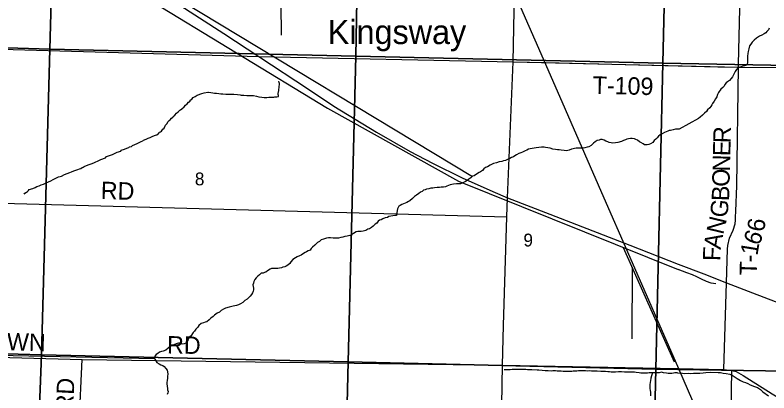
# Model space of a CAD drawing. Extents: x 1588073 to 2013523, y 1090242 to 1357120.
# Drawn here: x 1785512 to 1798510, y 1238801 to 1245314 of the extents above; entities that cross this region are included whole.
import ezdxf

# ---------------------------------------------------------------- set-up
doc = ezdxf.new("R2010")
doc.units = 0
for name, color, linetype in [('GM_X_County_Road', 7, 'Continuous'), ('GM_X_County_Road_Text', 7, 'Continuous'), ('GM_X_Interstate_Route', 7, 'Continuous'), ('GM_X_Minor_River', 7, 'Continuous'), ('GM_X_Rail_Line', 7, 'Continuous'), ('GM_X_Section', 7, 'Continuous'), ('GM_X_Section_Text', 7, 'Continuous'), ('GM_X_State_Route', 7, 'Continuous'), ('GM_X_Township', 7, 'Continuous'), ('GM_X_Township_Road', 7, 'Continuous'), ('GM_X_Township_Road_Text', 7, 'Continuous'), ('GM_X_Unincorporated_Text', 7, 'Continuous')]:
    doc.layers.add(name, color=color, linetype=linetype)

msp = doc.modelspace()

# ---------------------------------------------------------------- linework, layer by layer
at = {"layer": 'GM_X_County_Road'}
for points in [[(1783455, 1244777), (1789714, 1244599), (1794099, 1244508)], [(1783338, 1239471), (1786669, 1239379), (1793916, 1239280)], [(1793916, 1239280), (1796937, 1239222), (1797730, 1239206), (1797868, 1239189), (1797942, 1239170), (1798066, 1239102), (1798567, 1238786), (1799878, 1238002), (1800384, 1237717), (1800530, 1237645), (1800653, 1237609), (1800784, 1237606), (1801009, 1237631), (1801102, 1237626), (1801198, 1237597)], [(1797948, 1233819), (1797943, 1233923), (1797894, 1235681), (1797869, 1236898), (1797812, 1237011), (1797793, 1237062), (1797856, 1238490), (1797868, 1239189)]]:
    msp.add_lwpolyline(points, dxfattribs=at)
at = {"layer": 'GM_X_Interstate_Route'}
for points in [[(1785484, 1246915), (1785971, 1246718), (1786551, 1246463), (1787073, 1246207), (1787447, 1246011), (1788270, 1245539), (1789114, 1244996), (1789714, 1244599), (1790570, 1244034), (1791010, 1243743), (1791741, 1243297), (1792324, 1242961), (1792708, 1242760), (1793219, 1242506), (1793750, 1242273), (1794002, 1242166)], [(1794002, 1242166), (1794732, 1241883), (1796109, 1241345), (1796944, 1241022), (1797388, 1240851), (1797777, 1240701), (1798226, 1240528), (1798620, 1240376), (1799159, 1240168), (1799436, 1240060), (1799894, 1239880), (1800019, 1239834)]]:
    msp.add_lwpolyline(points, dxfattribs=at)
at = {"layer": 'GM_X_Minor_River'}
for p, q in [((1787308, 1245896), (1790896, 1243710)), ((1788371, 1245565), (1793400, 1242534)), ((1790097, 1245501), (1790098, 1244970)), ((1790896, 1243710), (1790896, 1243710)), ((1790896, 1243710), (1793156, 1242451)), ((1793156, 1242451), (1793156, 1242451)), ((1793156, 1242451), (1796942, 1240929)), ((1795997, 1241309), (1796878, 1239336)), ((1796149, 1240969), (1796147, 1239733)), ((1787915, 1239390), (1784794, 1239452))]:
    msp.add_line(p, q, dxfattribs=at)
for points in [[(1798512, 1245087), (1798502, 1245061), (1798471, 1245029), (1798455, 1245006), (1798428, 1244990), (1798390, 1244967), (1798345, 1244949), (1798296, 1244914), (1798257, 1244881), (1798223, 1244845), (1798196, 1244813), (1798177, 1244784), (1798164, 1244734), (1798154, 1244688), (1798147, 1244650), (1798142, 1244603), (1798139, 1244569), (1798138, 1244487), (1798121, 1244453), (1798087, 1244438), (1798059, 1244432), (1798030, 1244421), (1798006, 1244413), (1797982, 1244408), (1797951, 1244374), (1797930, 1244340), (1797912, 1244308), (1797897, 1244284), (1797883, 1244251), (1797860, 1244219), (1797827, 1244185), (1797797, 1244164), (1797770, 1244146), (1797748, 1244118), (1797737, 1244087), (1797713, 1244067), (1797682, 1244035), (1797641, 1243978), (1797624, 1243946), (1797611, 1243906), (1797587, 1243872), (1797564, 1243830), (1797539, 1243791), (1797524, 1243765), (1797506, 1243739), (1797493, 1243715), (1797453, 1243678), (1797434, 1243650), (1797401, 1243623), (1797365, 1243587), (1797324, 1243554), (1797293, 1243532), (1796964, 1243348)], [(1789023, 1243962), (1789059, 1243958), (1789073, 1243958), (1789095, 1243956), (1789145, 1243952), (1789207, 1243953), (1789281, 1243951), (1789349, 1243947), (1789391, 1243939), (1789411, 1243935), (1789433, 1243931), (1789455, 1243931), (1789509, 1243925), (1789563, 1243928), (1789625, 1243926), (1789673, 1243918), (1789717, 1243906), (1789767, 1243900), (1789805, 1243894), (1789820, 1243892), (1789852, 1243894), (1789886, 1243896), (1789934, 1243897), (1789958, 1243899), (1789972, 1243899), (1789992, 1243903), (1790010, 1243903), (1790028, 1243907), (1790052, 1243909), (1790054, 1243929), (1790049, 1243945), (1790047, 1243971), (1790055, 1243985), (1790059, 1244013), (1790061, 1244039), (1790063, 1244057), (1790067, 1244080), (1790071, 1244116), (1790071, 1244132), (1790067, 1244150), (1790057, 1244172)], [(1785668, 1242225), (1785682, 1242245), (1785710, 1242263), (1785728, 1242271), (1785744, 1242289), (1785756, 1242305), (1785818, 1242327), (1785856, 1242343), (1785888, 1242356), (1785926, 1242370), (1785964, 1242388), (1786000, 1242400), (1786039, 1242416), (1786089, 1242440), (1786127, 1242459), (1786167, 1242477), (1786205, 1242495), (1786259, 1242523), (1786287, 1242533), (1786315, 1242539), (1786365, 1242564), (1786459, 1242598), (1786485, 1242612), (1786525, 1242628), (1786593, 1242649), (1786625, 1242661), (1786645, 1242671), (1786671, 1242685), (1786687, 1242691), (1786701, 1242701), (1786775, 1242731), (1786841, 1242754), (1786883, 1242772), (1786903, 1242784), (1786931, 1242794), (1786989, 1242824), (1787069, 1242853), (1787087, 1242875), (1787191, 1242911), (1787271, 1242950), (1787333, 1242970), (1787343, 1242984), (1787399, 1243004), (1787441, 1243020), (1787471, 1243030), (1787487, 1243043), (1787517, 1243051), (1787539, 1243063), (1787579, 1243083), (1787620, 1243101), (1787688, 1243133), (1787714, 1243148), (1787728, 1243158), (1787770, 1243172), (1787784, 1243178), (1787804, 1243192), (1787822, 1243200), (1787842, 1243206), (1787888, 1243228), (1787934, 1243243), (1787954, 1243251), (1787992, 1243279), (1787998, 1243295), (1788020, 1243303), (1788034, 1243315), (1788060, 1243345), (1788080, 1243365), (1788104, 1243414), (1788130, 1243440), (1788154, 1243478), (1788170, 1243494), (1788184, 1243506), (1788210, 1243536), (1788232, 1243554), (1788238, 1243568), (1788268, 1243591), (1788293, 1243623), (1788323, 1243645), (1788353, 1243673), (1788367, 1243681), (1788389, 1243699), (1788425, 1243731), (1788451, 1243758), (1788479, 1243782), (1788501, 1243812), (1788529, 1243832), (1788533, 1243846), (1788561, 1243866), (1788583, 1243892), (1788605, 1243905), (1788619, 1243913), (1788653, 1243933), (1788731, 1243963), (1788773, 1243971), (1788835, 1243985), (1788849, 1243986), (1788885, 1243978), (1788919, 1243976), (1788951, 1243970), (1788983, 1243966), (1789023, 1243962)], [(1796964, 1243348), (1796928, 1243349), (1796900, 1243345), (1796856, 1243337), (1796812, 1243327), (1796788, 1243324), (1796764, 1243314), (1796736, 1243304), (1796708, 1243290), (1796667, 1243268), (1796637, 1243248), (1796607, 1243224), (1796583, 1243196), (1796561, 1243173), (1796533, 1243149), (1796506, 1243119), (1796470, 1243095), (1796438, 1243081), (1796412, 1243075), (1796366, 1243079), (1796342, 1243096), (1796302, 1243120), (1796278, 1243130), (1796244, 1243156), (1796214, 1243171), (1796190, 1243179), (1796150, 1243187), (1796122, 1243185), (1796086, 1243180), (1796058, 1243174), (1796034, 1243164), (1796000, 1243152), (1795966, 1243136), (1795902, 1243117), (1795867, 1243111), (1795817, 1243107), (1795791, 1243111), (1795755, 1243117), (1795731, 1243128), (1795699, 1243138), (1795670, 1243160), (1795634, 1243170), (1795608, 1243167), (1795581, 1243159), (1795549, 1243153), (1795513, 1243131), (1795483, 1243105), (1795443, 1243067), (1795406, 1243043), (1795378, 1243034), (1795336, 1243024), (1795308, 1243020), (1795272, 1243020), (1795232, 1243018), (1795208, 1243019), (1795184, 1243021), (1795106, 1243003), (1795064, 1242983), (1795018, 1242974), (1794978, 1242978), (1794928, 1242986), (1794892, 1242993), (1794866, 1242993), (1794829, 1242995), (1794786, 1243005), (1794736, 1243018), (1794698, 1243028), (1794660, 1243032), (1794636, 1243036), (1794587, 1243035), (1794545, 1243033), (1794495, 1243027), (1794461, 1243019), (1794427, 1243016), (1794395, 1243008), (1794365, 1243000), (1794333, 1242986), (1794309, 1242976), (1794285, 1242960), (1794259, 1242952), (1794232, 1242939), (1794200, 1242925), (1794156, 1242907), (1794128, 1242889), (1794104, 1242869), (1794070, 1242857), (1794040, 1242843), (1794015, 1242830), (1793967, 1242808), (1793931, 1242800), (1793903, 1242788), (1793857, 1242782), (1793815, 1242767), (1793763, 1242757), (1793728, 1242739), (1793704, 1242725), (1793658, 1242699), (1793624, 1242684), (1793596, 1242664), (1793570, 1242634), (1793535, 1242612)], [(1793535, 1242612), (1793511, 1242602), (1793465, 1242572), (1793427, 1242544), (1793401, 1242535), (1793369, 1242511), (1793334, 1242487), (1793306, 1242465), (1793278, 1242445), (1793232, 1242421), (1793190, 1242404), (1793152, 1242402), (1793124, 1242404), (1793073, 1242400), (1793041, 1242392), (1793013, 1242387), (1792985, 1242375), (1792959, 1242365), (1792933, 1242353), (1792899, 1242349), (1792861, 1242345), (1792827, 1242344), (1792787, 1242342), (1792745, 1242336), (1792715, 1242332), (1792681, 1242329), (1792646, 1242321), (1792604, 1242311), (1792580, 1242301), (1792556, 1242293), (1792532, 1242275), (1792502, 1242261), (1792474, 1242238), (1792431, 1242208), (1792401, 1242186), (1792363, 1242154), (1792321, 1242112), (1792293, 1242100), (1792264, 1242084), (1792240, 1242069), (1792210, 1242061), (1792178, 1242047), (1792154, 1242031), (1792128, 1242017), (1792103, 1241971), (1792095, 1241909), (1792087, 1241859), (1792061, 1241859), (1792023, 1241851), (1791992, 1241845), (1791958, 1241840), (1791932, 1241826), (1791894, 1241816), (1791854, 1241802), (1791824, 1241786), (1791796, 1241776), (1791772, 1241761), (1791751, 1241729), (1791721, 1241707), (1791689, 1241673), (1791655, 1241651), (1791621, 1241631), (1791593, 1241621), (1791558, 1241603), (1791514, 1241588), (1791482, 1241584), (1791420, 1241584), (1791394, 1241578), (1791346, 1241549), (1791312, 1241525), (1791285, 1241517), (1791261, 1241509), (1791237, 1241503), (1791195, 1241495), (1791163, 1241486), (1791127, 1241480), (1791091, 1241470), (1791065, 1241468), (1791033, 1241466), (1790999, 1241467), (1790953, 1241473), (1790917, 1241475), (1790879, 1241471), (1790828, 1241452), (1790790, 1241440), (1790762, 1241410), (1790728, 1241394), (1790706, 1241368), (1790678, 1241346), (1790643, 1241314), (1790617, 1241288), (1790599, 1241264), (1790565, 1241247), (1790539, 1241231), (1790515, 1241219), (1790470, 1241193), (1790446, 1241175), (1790416, 1241165), (1790378, 1241149), (1790348, 1241132), (1790302, 1241098)], [(1790302, 1241098), (1790269, 1241062), (1790251, 1241032), (1790217, 1241004), (1790185, 1240988), (1790161, 1240974), (1790128, 1240969), (1790104, 1240959), (1790074, 1240953), (1790042, 1240943), (1790000, 1240947), (1789962, 1240948), (1789934, 1240946), (1789908, 1240936), (1789862, 1240904), (1789838, 1240884), (1789811, 1240874), (1789787, 1240864), (1789755, 1240863), (1789727, 1240839), (1789697, 1240813), (1789669, 1240783), (1789644, 1240757), (1789628, 1240721), (1789624, 1240691), (1789614, 1240665), (1789620, 1240633), (1789623, 1240605), (1789625, 1240579), (1789615, 1240552), (1789607, 1240528), (1789587, 1240499), (1789566, 1240471), (1789516, 1240415), (1789476, 1240391), (1789440, 1240361), (1789399, 1240335), (1789365, 1240319), (1789329, 1240306), (1789271, 1240296), (1789201, 1240276), (1789139, 1240259), (1789108, 1240247), (1789068, 1240221), (1789038, 1240191), (1788998, 1240173), (1788952, 1240141), (1788925, 1240120), (1788885, 1240090), (1788857, 1240058), (1788819, 1240026), (1788789, 1240020), (1788758, 1240008), (1788718, 1240000), (1788682, 1239965), (1788662, 1239935), (1788630, 1239901), (1788605, 1239867), (1788585, 1239843), (1788541, 1239779), (1788512, 1239759), (1788496, 1239731), (1788488, 1239707), (1788456, 1239659), (1788426, 1239645), (1788394, 1239643), (1788360, 1239660), (1788332, 1239660), (1788304, 1239652), (1788263, 1239638), (1788229, 1239618), (1788189, 1239599), (1788153, 1239573), (1788111, 1239539), (1788068, 1239523), (1788034, 1239517), (1788000, 1239502), (1787974, 1239478), (1787946, 1239460), (1787924, 1239436), (1787915, 1239406), (1787923, 1239380), (1787937, 1239351), (1787959, 1239327), (1787997, 1239301), (1788025, 1239285), (1788059, 1239274), (1788085, 1239256), (1788112, 1239224), (1788136, 1239194), (1788144, 1239129), (1788142, 1239085), (1788139, 1239053), (1788135, 1239015), (1788127, 1238981), (1788129, 1238955), (1788132, 1238917), (1788140, 1238877), (1788142, 1238851), (1788150, 1238826), (1788144, 1238802)], [(1797592, 1240683), (1797511, 1240690), (1797432, 1240723), (1797346, 1240764), (1797268, 1240803), (1797190, 1240835), (1797096, 1240870), (1797018, 1240899), (1796944, 1240930)], [(1796935, 1239148), (1796890, 1239146), (1796866, 1239142), (1796838, 1239138), (1796804, 1239135), (1796770, 1239135), (1796742, 1239141), (1796690, 1239149), (1796658, 1239156), (1796616, 1239148), (1796590, 1239144), (1796444, 1239145), (1796418, 1239143), (1796360, 1239142), (1796332, 1239140), (1796302, 1239140), (1796274, 1239148), (1796218, 1239154), (1796194, 1239157), (1796168, 1239159), (1796133, 1239157), (1796091, 1239159), (1796049, 1239160), (1796021, 1239158), (1795965, 1239162), (1795915, 1239162), (1795867, 1239159), (1795827, 1239159), (1795787, 1239161), (1795761, 1239163), (1795733, 1239166), (1795693, 1239170), (1795609, 1239170), (1795551, 1239175), (1795503, 1239177), (1795453, 1239177), (1795417, 1239180), (1795375, 1239178), (1795349, 1239180), (1795311, 1239182), (1795271, 1239183), (1795225, 1239181), (1795196, 1239177), (1795170, 1239175), (1795136, 1239175), (1795110, 1239172), (1795042, 1239172), (1795012, 1239170), (1794962, 1239170), (1794930, 1239173), (1794898, 1239173), (1794858, 1239177), (1794830, 1239179), (1794784, 1239182), (1794756, 1239178), (1794702, 1239180), (1794676, 1239182), (1794652, 1239184), (1794598, 1239185), (1794542, 1239193), (1794516, 1239195), (1794420, 1239196), (1794380, 1239198), (1794346, 1239200), (1794316, 1239203), (1794288, 1239203), (1794262, 1239205), (1794220, 1239207), (1794185, 1239205), (1794147, 1239204), (1794113, 1239202), (1794083, 1239202), (1794051, 1239200), (1794027, 1239200), (1793997, 1239199), (1793971, 1239199), (1793945, 1239197)], [(1796500, 1239145), (1796483, 1239093), (1796471, 1239053), (1796465, 1239008), (1796461, 1238984), (1796458, 1238938), (1796458, 1238876), (1796464, 1238844), (1796468, 1238814), (1796467, 1238752)], [(1796935, 1239148), (1797021, 1239139), (1797059, 1239138), (1797115, 1239139), (1797159, 1239138), (1797209, 1239139), (1797250, 1239143), (1797320, 1239143), (1797378, 1239146), (1797421, 1239155), (1797495, 1239158), (1797634, 1239155), (1797674, 1239153), (1797722, 1239142), (1797772, 1239135), (1797836, 1239125), (1797874, 1239107), (1797961, 1239047), (1798021, 1239014), (1798064, 1238993), (1798108, 1238980), (1798148, 1238963), (1798188, 1238942), (1798258, 1238909), (1798314, 1238892), (1798363, 1238862), (1798405, 1238817), (1798500, 1238753)], [(1788144, 1238802), (1788133, 1238776)]]:
    msp.add_lwpolyline(points, dxfattribs=at)
at = {"layer": 'GM_X_Rail_Line'}
msp.add_lwpolyline([(1790814, 1253266), (1791193, 1252402), (1791603, 1251462), (1791761, 1251098), (1792019, 1250510), (1792365, 1249715), (1792807, 1248704), (1793591, 1246908), (1794615, 1244562), (1794995, 1243693), (1795662, 1242164), (1796071, 1241232), (1796948, 1239221), (1797268, 1238492)], dxfattribs=at)
at = {"layer": 'GM_X_Section'}
for points in [[(1786253, 1249853), (1786110, 1244725), (1781125, 1244881), (1781261, 1250001)], [(1791482, 1249727), (1791389, 1244607), (1786110, 1244725), (1786253, 1249853)], [(1791556, 1249724), (1796800, 1249618), (1796681, 1244482), (1791389, 1244607), (1791482, 1249727)], [(1796800, 1249618), (1796832, 1249616), (1802113, 1249526), (1801959, 1244386), (1796681, 1244482)], [(1781125, 1244881), (1786110, 1244725), (1785968, 1239459), (1780948, 1239599), (1781123, 1244701)], [(1786110, 1244725), (1791389, 1244607), (1791254, 1239334), (1785968, 1239459)], [(1791389, 1244607), (1796681, 1244482), (1796561, 1239208), (1791254, 1239334)], [(1796681, 1244482), (1801959, 1244386), (1801871, 1239129), (1801855, 1239130), (1796561, 1239208)], [(1785968, 1239459), (1785758, 1234139), (1780755, 1234157), (1780939, 1239421), (1780948, 1239599)], [(1791254, 1239334), (1791128, 1234074), (1785758, 1234139), (1785968, 1239459)], [(1796561, 1239208), (1796440, 1233926), (1791128, 1234074), (1791254, 1239334)], [(1796561, 1239208), (1801855, 1239130), (1801831, 1237295), (1801815, 1236264), (1797917, 1236344), (1797908, 1233923), (1796440, 1233926)]]:
    msp.add_lwpolyline(points, close=True, dxfattribs=at)
at = {"layer": 'GM_X_State_Route'}
for points in [[(1794099, 1244508), (1794151, 1247152), (1794160, 1247493), (1794187, 1249107), (1794191, 1249527), (1794189, 1249670), (1794207, 1250354), (1794198, 1252721), (1794198, 1252735)], [(1793935, 1239962), (1793989, 1241838), (1794002, 1242166), (1794099, 1244508)], [(1793832, 1234111), (1793916, 1239280), (1793935, 1239962)]]:
    msp.add_lwpolyline(points, dxfattribs=at)
at = {"layer": 'GM_X_Township'}
for points in [[(1780849, 1236733), (1781100, 1244734), (1781104, 1244875), (1781375, 1244859), (1783455, 1244777), (1789714, 1244599), (1794099, 1244508), (1797984, 1244413), (1801961, 1244392)], [(1783455, 1244777), (1789714, 1244599), (1794099, 1244508), (1797984, 1244413), (1801961, 1244392)]]:
    msp.add_lwpolyline(points, dxfattribs=at)
at = {"layer": 'GM_X_Township_Road'}
for points in [[(1797985, 1244466), (1798047, 1247099)], [(1794099, 1244508), (1794661, 1244494)], [(1794661, 1244494), (1797626, 1244422)], [(1797626, 1244422), (1797984, 1244413)], [(1797937, 1241902), (1797937, 1241935), (1797958, 1242371), (1797984, 1244413), (1797985, 1244466), (1797985, 1244466)], [(1783374, 1242121), (1793989, 1241838)], [(1797730, 1239206), (1797777, 1240701), (1797796, 1241277), (1797799, 1241341), (1797828, 1241468), (1797891, 1241607), (1797930, 1241715), (1797935, 1241780), (1797936, 1241862), (1797937, 1241902)], [(1786568, 1237149), (1786669, 1239379)]]:
    msp.add_lwpolyline(points, dxfattribs=at)

# ---------------------------------------------------------------- texts
at = {"layer": 'GM_X_County_Road_Text'}
for s, rotation, p in [('BOOKTOWN', 358.35, (1783652, 1239586)), ('RD', 359.0128, (1788130, 1239481))]:
    msp.add_text(s, height=300, rotation=rotation, dxfattribs=at).set_placement(p)
at = {"layer": 'GM_X_Section_Text'}
for s, p in [('8', (1788612, 1242379)), ('9', (1794277, 1241325))]:
    msp.add_text(s, height=221, rotation=0, dxfattribs=at).set_placement(p)
at = {"layer": 'GM_X_Township_Road_Text'}
for s, rotation, p in [('T-109', 358.5957, (1795467, 1243959)), ('R', 88.5284, (1797848, 1243103)), ('E', 88.5326, (1797843, 1242879)), ('N', 88.5281, (1797836, 1242615)), ('O', 88.5306, (1797829, 1242351)), ('RD', 358.5175, (1786987, 1242143)), ('B', 88.3757, (1797822, 1242104)), ('G', 83.1541, (1797788, 1241812)), ('N', 76.5142, (1797720, 1241518)), ('6', 80.9498, (1798424, 1241565)), ('A', 80.0825, (1797676, 1241263)), ('6', 68.1995, (1798336, 1241324)), ('F', 88.6172, (1797672, 1241072)), ('1', 80.8491, (1798311, 1241158)), ('-', 88.2591, (1798308, 1241045)), ('T', 88.2812, (1798302, 1240821)), ('RD', 87.0388, (1786509, 1238475))]:
    msp.add_text(s, height=300, rotation=rotation, dxfattribs=at).set_placement(p)
at = {"layer": 'GM_X_Unincorporated_Text'}
msp.add_text('Kingsway', height=417, rotation=0, dxfattribs=at).set_placement((1790904, 1244814))

doc.saveas('drawing.dxf')
